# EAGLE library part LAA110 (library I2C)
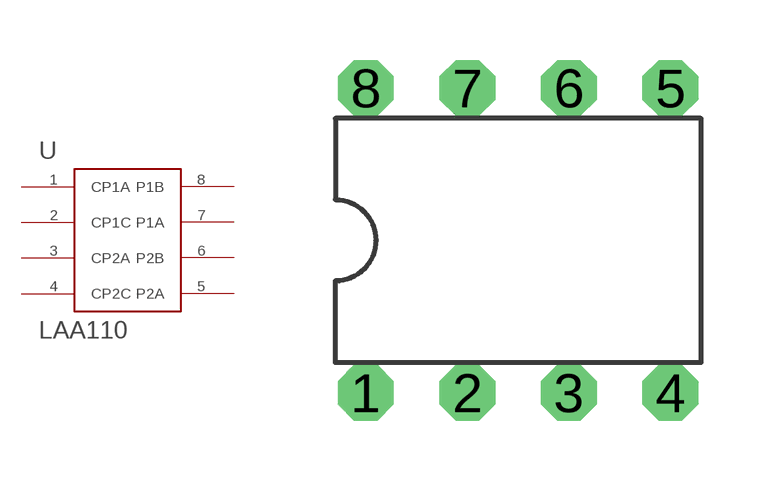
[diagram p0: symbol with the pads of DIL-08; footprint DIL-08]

Designator prefix U

## LAA110  [DIL-08]
1  CP1A  pas
2  CP1C  pas
3  CP2A  pas
4  CP2C  pas
5  P2A  pas
6  P2B  pas
7  P1A  pas
8  P1B  pas

## Footprint DIL-08 (pad centres in mm)
drill 0.813 pad 1.397 octagon: 1 0,0; 2 2.54,0; 3 5.08,0; 4 7.62,0; 5 7.62,7.62; 6 5.08,7.62; 7 2.54,7.62; 8 0,7.62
